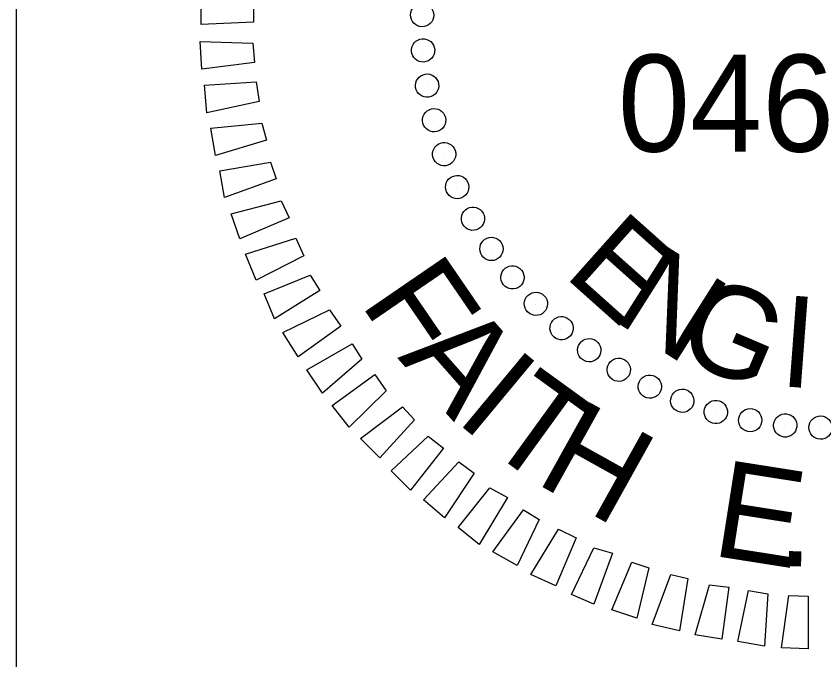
# Model space of a CAD drawing. Extents: x 1860868 to 1863318, y 1193312 to 1194425.
# Drawn here: x 1863048.87 to 1863098.83, y 1194178.74 to 1194218.55 of the extents above; entities that cross this region are included whole.
import ezdxf

# ---------------------------------------------------------------- set-up
doc = ezdxf.new("R2010")
doc.units = 0
doc.layers.add('Sheet PE Seal CELL', color=7, linetype='Continuous')
doc.layers.add('Sheet Plan CELL', color=7, linetype='Continuous')

msp = doc.modelspace()

# ---------------------------------------------------------------- linework, layer by layer
at = {"layer": 'Sheet PE Seal CELL'}
for p, q in [((1863074.013, 1194216.431), (1863074.013, 1194216.431)), ((1863074.313, 1194214.281), (1863074.313, 1194214.281)), ((1863074.713, 1194212.081), (1863074.713, 1194212.081)), ((1863075.313, 1194209.981), (1863075.313, 1194209.981)), ((1863076.113, 1194207.981), (1863076.113, 1194207.981)), ((1863077.113, 1194206.031), (1863077.113, 1194206.031)), ((1863078.263, 1194204.131), (1863078.263, 1194204.131)), ((1863079.513, 1194202.381), (1863079.513, 1194202.381)), ((1863081.013, 1194200.731), (1863081.013, 1194200.731)), ((1863082.563, 1194199.231), (1863082.563, 1194199.231)), ((1863084.313, 1194197.881), (1863084.313, 1194197.881)), ((1863086.113, 1194196.631), (1863086.113, 1194196.631)), ((1863088.063, 1194195.631), (1863088.063, 1194195.631)), ((1863090.063, 1194194.731), (1863090.063, 1194194.731)), ((1863092.163, 1194194.031), (1863092.163, 1194194.031)), ((1863094.263, 1194193.581), (1863094.263, 1194193.581)), ((1863096.413, 1194193.231), (1863096.413, 1194193.231)), ((1863098.613, 1194193.081), (1863098.613, 1194193.081))]:
    msp.add_line(p, q, dxfattribs=at)
for points in [[(1863063.563, 1194218.181), (1863060.313, 1194218.031), (1863060.313, 1194219.731), (1863063.563, 1194219.381)], [(1863063.613, 1194215.681), (1863060.363, 1194215.281), (1863060.263, 1194216.981), (1863063.513, 1194216.881)], [(1863063.913, 1194213.281), (1863060.663, 1194212.581), (1863060.513, 1194214.281), (1863063.713, 1194214.481)], [(1863064.363, 1194210.881), (1863061.213, 1194209.931), (1863060.913, 1194211.631), (1863064.063, 1194211.931)], [(1863064.963, 1194208.481), (1863061.763, 1194207.331), (1863061.463, 1194208.981), (1863064.613, 1194209.531)], [(1863065.763, 1194206.081), (1863062.713, 1194204.781), (1863062.163, 1194206.331), (1863065.263, 1194207.131)], [(1863066.663, 1194203.731), (1863063.713, 1194202.231), (1863063.063, 1194203.831), (1863066.163, 1194204.831)], [(1863067.663, 1194201.581), (1863064.863, 1194199.831), (1863064.213, 1194201.381), (1863067.063, 1194202.531)], [(1863068.963, 1194199.381), (1863066.313, 1194197.481), (1863065.363, 1194198.981), (1863068.263, 1194200.381)], [(1863070.263, 1194197.331), (1863067.813, 1194195.231), (1863066.863, 1194196.681), (1863069.663, 1194198.281)], [(1863071.763, 1194195.381), (1863069.463, 1194193.131), (1863068.413, 1194194.481), (1863071.063, 1194196.381)], [(1863073.513, 1194193.581), (1863071.363, 1194191.231), (1863070.163, 1194192.431), (1863072.763, 1194194.381)], [(1863075.313, 1194191.831), (1863073.263, 1194189.231), (1863072.063, 1194190.431), (1863074.363, 1194192.581)], [(1863077.213, 1194190.281), (1863075.363, 1194187.531), (1863074.063, 1194188.631), (1863076.263, 1194190.981)], [(1863079.263, 1194188.781), (1863077.513, 1194185.881), (1863076.213, 1194186.931), (1863078.163, 1194189.381)], [(1863081.213, 1194187.431), (1863079.863, 1194184.581), (1863078.363, 1194185.431), (1863080.263, 1194188.031)], [(1863083.513, 1194186.281), (1863082.263, 1194183.331), (1863080.713, 1194184.031), (1863082.413, 1194186.831)], [(1863085.763, 1194185.331), (1863084.613, 1194182.181), (1863083.213, 1194182.781), (1863084.613, 1194185.681)], [(1863088.013, 1194184.431), (1863087.263, 1194181.331), (1863085.713, 1194181.831), (1863086.963, 1194184.781)], [(1863090.413, 1194183.781), (1863089.913, 1194180.531), (1863088.213, 1194180.931), (1863089.363, 1194184.031)], [(1863092.963, 1194183.231), (1863092.513, 1194180.031), (1863090.863, 1194180.281), (1863091.763, 1194183.381)], [(1863095.363, 1194182.831), (1863095.163, 1194179.581), (1863093.513, 1194179.881), (1863094.163, 1194183.031)], [(1863097.863, 1194182.681), (1863097.863, 1194179.431), (1863096.213, 1194179.481), (1863096.663, 1194182.731)]]:
    msp.add_lwpolyline(points, close=True, dxfattribs=at)
for centre, major_axis in [((1863073.987, 1194218.619), (-0.72, 0.013)), ((1863074.044, 1194216.432), (-0.718, -0.05)), ((1863074.292, 1194214.258), (-0.711, -0.113)), ((1863074.728, 1194212.114), (-0.699, -0.174)), ((1863075.349, 1194210.016), (-0.681, -0.234)), ((1863076.151, 1194207.98), (-0.658, -0.293)), ((1863077.128, 1194206.022), (-0.63, -0.349)), ((1863078.271, 1194204.157), (-0.597, -0.403)), ((1863079.572, 1194202.398), (-0.56, -0.453)), ((1863081.022, 1194200.759), (-0.518, -0.5)), ((1863082.609, 1194199.253), (-0.472, -0.543)), ((1863084.321, 1194197.891), (-0.423, -0.582)), ((1863086.146, 1194196.683), (-0.371, -0.617)), ((1863088.069, 1194195.639), (-0.316, -0.647)), ((1863090.075, 1194194.767), (-0.258, -0.672)), ((1863092.15, 1194194.073), (-0.198, -0.692)), ((1863094.277, 1194193.562), (-0.137, -0.707)), ((1863096.441, 1194193.239), (-0.075, -0.716)), ((1863098.625, 1194193.105), (-0.013, -0.72))]:
    msp.add_ellipse(centre, major_axis=major_axis, ratio=0.999708, dxfattribs=at)
at = {"layer": 'Sheet Plan CELL'}
msp.add_line((1863048.874, 1193362.487), (1863048.898, 1194387.485), dxfattribs=at)

# ---------------------------------------------------------------- texts
at = {"layer": 'Sheet PE Seal CELL'}
msp.add_text('046981', height=5.9982, dxfattribs=at).set_placement((1863086.092, 1194210.173))
for s, height, rotation, p in [('E', 5.638, 318.2769, (1863082.663, 1194202.531)), ('N', 5.638, 327.634, (1863085.663, 1194199.831)), ('F', 5.998, 304.4142, (1863070.095, 1194200.837)), ('G', 5.638, 336.9902, (1863089.463, 1194197.581)), ('I', 5.638, 355.7012, (1863096.013, 1194195.681)), ('A', 5.998, 311.4309, (1863072.43, 1194197.428)), ('I', 5.998, 320.2712, (1863075.936, 1194193.582)), ('T', 5.998, 324.0731, (1863077.618, 1194192.102)), ('H', 5.998, 330.8733, (1863080.857, 1194189.747)), ('E', 5.998, 351.0577, (1863091.786, 1194185.211)), ('.', 5.998, 358.167, (1863095.923, 1194184.564))]:
    msp.add_text(s, height=height, rotation=rotation, dxfattribs=at).set_placement(p)

doc.saveas('drawing.dxf')
